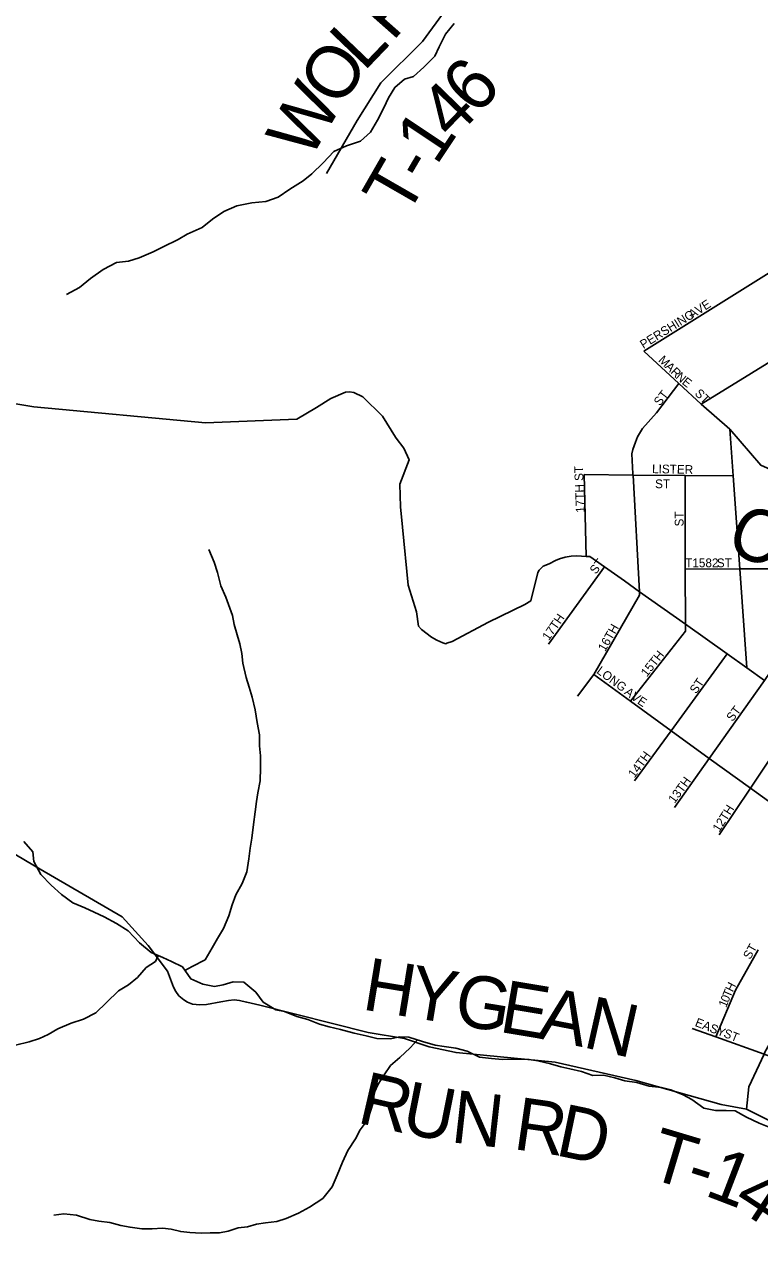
# Model space of a CAD drawing. Extents: x 1624196 to 2029251, y 146837 to 440034.
# Drawn here: x 1811228 to 1815416, y 273733 to 280739 of the extents above; entities that cross this region are included whole.
import ezdxf

# ---------------------------------------------------------------- set-up
doc = ezdxf.new("R2010")
doc.units = 0
for name, color, linetype in [('GM_X_County_Road', 7, 'Continuous'), ('GM_X_County_Road_Text', 7, 'Continuous'), ('GM_X_Minor_River', 7, 'Continuous'), ('GM_X_Township_Road', 7, 'Continuous'), ('GM_X_Township_Road_Text', 7, 'Continuous'), ('GM_X_Township_Subdivision', 7, 'Continuous'), ('GM_X_Township_Subdivision_Text', 7, 'Continuous')]:
    doc.layers.add(name, color=color, linetype=linetype)

msp = doc.modelspace()

# ---------------------------------------------------------------- linework, layer by layer
at = {"layer": 'GM_X_County_Road'}
for points in [[(1815247.1, 278432.8), (1815084.2, 278575.3), (1815920.9, 279089.6), (1816366.6, 279359.3), (1816614.9, 279007.9), (1816807.1, 279297), (1816979.5, 279252.7), (1817413.2, 279141), (1818042.4, 278972.6), (1818312.3, 278897.2), (1818447.3, 278884.8), (1818910.9, 278729.9), (1818861.8, 278488.5), (1819118.2, 278302.8), (1819417.6, 278085.8), (1819681.5, 277894.5), (1819933.5, 277729.6)], [(1811027, 278601), (1811280.7, 278559.4), (1812258.9, 278468.9), (1812779.5, 278490.3), (1812891.5, 278555.7), (1812973.4, 278606.8), (1813057.5, 278643.8), (1813079.9, 278645.4), (1813104.3, 278641), (1813156.3, 278616.7), (1813268, 278507.3), (1813341.6, 278387.6), (1813345.6, 278381.6), (1813390.4, 278323.8), (1813419.2, 278257.8), (1813366.3, 278118.6), (1813371.5, 277990.2), (1813382.8, 277873.8), (1813414.1, 277542.7), (1813461.9, 277390.5), (1813472.7, 277310.3), (1813490, 277290.7), (1813547.7, 277246.8), (1813577.5, 277229.1), (1813612, 277213.6), (1813623.1, 277210.5), (1813628.5, 277209.4), (1813635.4, 277211.7), (1813665.7, 277221.8), (1813872.6, 277332.4), (1814079.4, 277433), (1814112.8, 277453.3), (1814153.4, 277616.4), (1814160.1, 277628.8), (1814183.9, 277651), (1814217.9, 277665.5), (1814253.4, 277683.3), (1814277.3, 277694), (1814309, 277703.3), (1814343.5, 277708.8), (1814375.7, 277709.9), (1814376.1, 277709.9)], [(1815444.7, 277000.2), (1815345.2, 277072.1), (1815304.5, 277635.6), (1815266.3, 278165.9), (1815247.1, 278432.8)], [(1815247.1, 278432.8), (1815423.7, 278227.2), (1816086.3, 277932.4), (1816701, 277654.8), (1816789.8, 277607), (1816744.5, 277510.1), (1816661.4, 277372.7), (1816616.5, 277231.7), (1816607.8, 277145.5), (1816808.4, 276944.6), (1816903.8, 276849.1), (1817003, 276749.7), (1817272.5, 276611), (1817397.8, 276546.5), (1817554.1, 276467.1), (1817826.8, 276328.4), (1818051, 276214.5), (1818395, 276059.2), (1818745, 275886.4), (1818800.4, 275855.4), (1819072.9, 275695.9), (1819214.6, 275616.1)], [(1814376.1, 277709.9), (1814428.4, 277707), (1814450.1, 277705.8), (1814533.4, 277647.1), (1814646.6, 277567.2), (1814732.7, 277506.2), (1814994.3, 277320.8), (1815233.3, 277151.4), (1815345.2, 277072.1)]]:
    msp.add_lwpolyline(points, dxfattribs=at)
at = {"layer": 'GM_X_Minor_River'}
for points in [[(1813676.2, 280746.2), (1813627.6, 280684.2), (1813591, 280612.2), (1813566.6, 280560.2), (1813504, 280496.3), (1813445.4, 280442.5), (1813393.1, 280428.8), (1813338.6, 280380.9), (1813302.1, 280321), (1813275.6, 280264.9), (1813239.1, 280194.9), (1813200.5, 280126.9), (1813141.9, 280075.1), (1813063.5, 280047.5), (1812991, 280015.8), (1812930.4, 279951.9), (1812865.7, 279888.1), (1812815.3, 279848.2), (1812740.7, 279800.5), (1812674.2, 279754.8), (1812603.8, 279731.1), (1812523.4, 279723.6), (1812437, 279706), (1812364.5, 279674.3), (1812300, 279630.6), (1812239.5, 279582.8), (1812155, 279545.2), (1812102.6, 279513.4), (1812018, 279471.7), (1811961.6, 279444), (1811881.1, 279410.3), (1811820.8, 279390.6), (1811752.5, 279383), (1811676, 279343.3), (1811603.4, 279291.6), (1811540.8, 279239.8), (1811466.3, 279200.1)], [(1812141.7, 275347.1), (1812183.9, 275368.9), (1812256.4, 275406.6), (1812297, 275474.6), (1812327.4, 275528.6), (1812361.9, 275586.6), (1812392.5, 275658.6), (1812411, 275720.8), (1812431.4, 275776.8), (1812468, 275842.8), (1812494.5, 275908.9), (1812507, 275983.1), (1812513.4, 276043.2), (1812523.9, 276101.4), (1812532.4, 276179.6), (1812542.9, 276251.8), (1812549.3, 276309.9), (1812557.7, 276360), (1812570.2, 276428.2), (1812572.6, 276502.4), (1812573.1, 276570.7), (1812567.4, 276626.9), (1812567.8, 276689.1), (1812554.3, 276759.4), (1812542.7, 276831.7), (1812525.1, 276904.1), (1812507.4, 276962.4), (1812491.7, 277016.6), (1812472.2, 277099), (1812466.5, 277153.2), (1812454.8, 277209.5), (1812439.1, 277259.8), (1812423.4, 277318.1), (1812413.7, 277370.3), (1812374.3, 277474.9), (1812346.6, 277539.3), (1812327, 277615.6), (1812309.3, 277673.9), (1812277.7, 277746.4)], [(1815481.7, 274450.2), (1815415.6, 274476.7), (1815343.5, 274509.2), (1815277.5, 274545.7), (1815227.4, 274548), (1815165.2, 274548.4), (1815099, 274560.8), (1815031.1, 274611.4), (1814981.1, 274637.8), (1814911, 274666.3), (1814858.9, 274678.7), (1814788.7, 274687.1), (1814718.6, 274707.6), (1814648.4, 274718.1), (1814592.3, 274734.5), (1814528.2, 274748.9), (1814466, 274747.2), (1814401.9, 274769.7), (1814335.8, 274786.1), (1814283.6, 274796.5), (1814225.5, 274814.9), (1814153.4, 274831.4), (1814103.3, 274839.7), (1814027, 274840.2), (1813952.7, 274838.6), (1813888.5, 274845), (1813820.3, 274851.4), (1813750.3, 274886), (1813686.2, 274904.4), (1813620, 274912.8), (1813567.9, 274921.2), (1813495.8, 274941.7), (1813417.7, 274966.2), (1813367.5, 274968.5), (1813311.2, 274956.8), (1813235, 274959.3), (1813174.8, 274973.7), (1813106.7, 274988.1), (1813028.6, 275010.7), (1812964.4, 275025.1), (1812908.3, 275039.5), (1812842.3, 275066), (1812780.2, 275084.4), (1812710.1, 275112.9), (1812660, 275121.3), (1812588, 275165.8), (1812546.2, 275222.3), (1812478.4, 275278.9), (1812416.1, 275281.2), (1812359.8, 275265.5), (1812309.6, 275255.8), (1812243.4, 275268.2), (1812175.4, 275298.7), (1812127.7, 275367.2), (1812065.7, 275397.7), (1812015.6, 275420.1), (1811949.6, 275448.6), (1811883.7, 275503.1), (1811817.9, 275571.8), (1811751.9, 275614.3), (1811682, 275652.9), (1811623.9, 275679.3), (1811571.9, 275703.7), (1811503.8, 275732.2), (1811437.9, 275778.7), (1811380.1, 275833.3), (1811320.2, 275893.8), (1811280.6, 275968.3), (1811274.9, 276022.5), (1811223.1, 276081)], [(1811990.2, 275431.1), (1811973.3, 275398.3), (1811920.9, 275362.5), (1811872.4, 275306.6), (1811819.9, 275264.7), (1811763.5, 275231), (1811694.8, 275163.1), (1811634.2, 275105.3), (1811563.7, 275069.6), (1811493.3, 275045.9), (1811416.9, 275014.3), (1811362.4, 274980.5), (1811312.1, 274958.7), (1811253.8, 274939), (1811175.4, 274921.4)], [(1813468.3, 274950.3), (1813425.3, 274906), (1813366.7, 274850.1), (1813314.2, 274804.3), (1813277.8, 274752.3), (1813243.3, 274698.4), (1813220.9, 274648.3), (1813216.5, 274598.2), (1813200.1, 274544.1), (1813179.7, 274492), (1813141.2, 274438.1), (1813114.8, 274386.1), (1813070.2, 274320.1), (1813039.7, 274254.1), (1813009.1, 274180), (1812980.5, 274112), (1812927.9, 274046), (1812851.3, 273996.3), (1812788.9, 273962.6), (1812718.5, 273932.9), (1812666.1, 273915.2), (1812601.9, 273907.5), (1812549.6, 273899.8), (1812499.4, 273884), (1812445.1, 273878.3), (1812388.8, 273860.6), (1812338.6, 273850.9), (1812286.4, 273851.2), (1812234.2, 273849.5), (1812170, 273851.9), (1812117.8, 273858.2), (1812063.7, 273870.6), (1812013.6, 273876.9), (1811955.4, 273873.2), (1811897.1, 273873.6), (1811829, 273882), (1811776.8, 273892.4), (1811714.7, 273908.8), (1811650.6, 273917.2), (1811600.4, 273927.5), (1811524.3, 273952.1), (1811452.1, 273958.5), (1811393.9, 273950.8)]]:
    msp.add_lwpolyline(points, dxfattribs=at)
at = {"layer": 'GM_X_Township_Road'}
for points in [[(1812948.9, 279890), (1813122.9, 280193.1), (1813257.6, 280407.3), (1813496.6, 280642.7), (1813744.6, 280984.7), (1813868.8, 281239.1), (1813940.4, 281531), (1813981.8, 281820.7), (1814011.3, 281909.5), (1814070.7, 281984.3), (1814277.3, 282245.5), (1814452.4, 282444.1), (1814585.6, 282600.2), (1814782.5, 282821.1), (1814847.3, 282919), (1814875.4, 282986.7), (1814920.9, 283266.4), (1814929.3, 283445.2), (1814959.9, 283608.3)], [(1812494.3, 275165.3), (1812493.8, 275165.4), (1812453.8, 275174.8), (1812423.5, 275179.7), (1812390.1, 275175.2), (1812347.3, 275167.7), (1812265, 275152.8), (1812227.7, 275150.8), (1812185.5, 275155.2), (1812156.5, 275166.3), (1812136.5, 275179.7), (1812107.6, 275201.9), (1812089.8, 275226.4), (1812077, 275251.3), (1812041.9, 275343.4), (1811931.9, 275488.9), (1811783.6, 275652.1), (1811316.4, 275924.5), (1811140.4, 276029.2), (1810954.3, 276151.8), (1810793.5, 276351)], [(1816071.5, 273721.2), (1816095.5, 273940.3), (1816134.3, 274085.3), (1816137.5, 274165.7), (1816108.9, 274219.7), (1816077, 274258.8), (1816011.4, 274319.1), (1815832.1, 274351.5), (1815727.5, 274358.4), (1815650.9, 274373.7), (1815604.7, 274478), (1815478.9, 274486.5), (1815342.8, 274555.2), (1815198.4, 274582), (1814712.4, 274719.7), (1814253, 274823.5), (1813687.4, 274878), (1813534.2, 274910.6), (1813393, 274959.4), (1813185.5, 274993.4), (1812568.7, 275147.9), (1812494.3, 275165.3)]]:
    msp.add_lwpolyline(points, dxfattribs=at)
at = {"layer": 'GM_X_Township_Subdivision'}
for points in [[(1814756.7, 278878.1), (1815684.2, 279456.8), (1816409.7, 279896.6), (1816625.1, 280026.4), (1816695.5, 280050.2)], [(1815084.2, 278575.3), (1814957.8, 278692.2), (1814756.7, 278878.1)], [(1814695.7, 278177.1), (1814689.8, 278292.8), (1814694.3, 278317.7), (1814709.2, 278359.3), (1814721, 278388.8), (1814750.7, 278436), (1814830.3, 278525.2), (1814957.8, 278692.2)], [(1814379.5, 276909.7), (1814472.3, 277034.1), (1814733.8, 277485.8), (1814732.7, 277506.2), (1814696, 278171), (1814695.7, 278177.1)], [(1814417.5, 278173.5), (1814696, 278171), (1814992.8, 278168.4), (1815266.3, 278165.9)], [(1814428.4, 277707), (1814417.5, 278173.5)], [(1814681.5, 276882.1), (1814994.4, 277280.2), (1814994.3, 277320.8), (1814993.8, 277635), (1814992.8, 278168.4)], [(1814213.7, 277207.3), (1814533.4, 277647.1)], [(1814993.8, 277635), (1815304.5, 277635.6), (1815484.5, 277636)], [(1814933.3, 276275.7), (1815130.9, 276555.6), (1815444.7, 277000.2), (1815481.4, 277052.1), (1815646.9, 277270)], [(1814705, 276427), (1814913.8, 276713.3), (1815233.3, 277151.4)], [(1814472.3, 277034.1), (1814681.5, 276882.1), (1814913.8, 276713.3), (1815130.9, 276555.6), (1815364.7, 276385.7), (1815605.5, 276212.7), (1815833.6, 276048.9), (1816071.1, 275878.3), (1816299, 275714.6), (1816551.4, 275545.4), (1816792.9, 275383.7)], [(1815187.4, 276119.9), (1815364.7, 276385.7), (1815667.3, 276839.3), (1815755.6, 276971.7)], [(1815168.3, 274967.6), (1815280.6, 275233.6), (1815409, 275463.9)], [(1815342.8, 274555.2), (1815356.9, 274682.3), (1815442.6, 274868.8), (1815448.1, 274880.7), (1815733.3, 275389.7)], [(1815033.3, 275016.2), (1815168.3, 274967.6), (1815442.6, 274868.8), (1815766.2, 274752.3)]]:
    msp.add_lwpolyline(points, dxfattribs=at)

# ---------------------------------------------------------------- texts
at = {"layer": 'GM_X_County_Road_Text'}
msp.add_text('C-440', height=300, rotation=336.01021, dxfattribs=at).set_placement((1815212, 277749.6))
at = {"layer": 'GM_X_Township_Road_Text'}
for s, rotation, p in [('F', 48.522, (1813325.2, 280639)), ('L', 46.24556, (1813161.2, 280467.3)), ('O', 56.8848, (1813026.2, 280257.7)), ('6', 47.94539, (1813804.9, 280214.3)), ('W', 59.81415, (1812853.5, 279960.7)), ('4', 45.85004, (1813668, 280073)), ('1', 56.32436, (1813574.7, 279930.5)), ('T', 60.11744, (1813403.3, 279634.1)), ('-', 59.6132, (1813514.8, 279828.1)), ('H', 350.72153, (1813145.5, 275125.3)), ('Y', 350.72267, (1813406.1, 275082.7)), ('G', 350.72267, (1813666.6, 275040.2)), ('E', 350.47638, (1813926.8, 274997.6)), ('A', 348.89653, (1814146, 274960.9)), ('N', 347.28115, (1814402.9, 274910.5)), ('R', 346.989, (1813116.4, 274480.6)), ('U', 348.8275, (1813366.6, 274422.9)), ('N', 353.57091, (1813651.9, 274367.7)), ('R', 351.75757, (1814007.8, 274329.2)), ('D', 348.19605, (1814246.8, 274294.8)), ('T', 343.33319, (1814770.1, 274166.9)), ('1', 338.96156, (1815096.7, 274066.9)), ('-', 342.23526, (1814983.6, 274103)), ('4', 326.66067, (1815254, 274008.3))]:
    msp.add_text(s, height=300, rotation=rotation, dxfattribs=at).set_placement(p)
at = {"layer": 'GM_X_Township_Subdivision_Text'}
for s, rotation, p in [('AVE', 32.62284, (1815032.2, 279060.7)), ('PERSHING', 31.82754, (1814755.1, 278889.2)), ('M', 316.05615, (1814837, 278822)), ('A', 316.04332, (1814875, 278785.3)), ('R', 316.04619, (1814906.7, 278754.8)), ('N', 317.35874, (1814936.1, 278726.4)), ('E', 321.38924, (1814971.4, 278694.1)), ('ST', 52.43303, (1814849.4, 278561.4)), ('ST', 314.99504, (1815043.9, 278632.7)), ('17TH ST', 92.20139, (1814420.7, 277956.8)), ('LISTER', 358.77875, (1814804.3, 278182.2)), ('ST', 0.00001, (1814821.7, 278096.2)), ('ST', 90, (1814983.9, 277878)), ('ST', 53.13155, (1814484.2, 277602.1)), ('T1582', 0.00001, (1814993.3, 277645.4)), ('ST', 0.00001, (1815173.7, 277645.4)), ('17TH', 55.30353, (1814215.5, 277223.4)), ('16TH', 60.25679, (1814536.3, 277161.1)), ('15TH', 51.34125, (1814774.7, 277017.1)), ('LONG', 323.4302, (1814484.1, 277045.2)), ('ST', 55.30921, (1815055.9, 276919.8)), ('A', 321.73964, (1814642.8, 276926.1)), ('V', 324.83698, (1814679.7, 276897.1)), ('E', 326.27089, (1814716.8, 276871)), ('ST', 52.42653, (1815263, 276761.8)), ('14TH', 53.83939, (1814704.1, 276440.4)), ('13TH', 53.84687, (1814932.9, 276295.2)), ('12TH', 57.80544, (1815187.7, 276131.8)), ('ST', 60.25679, (1815363.5, 275405.5)), ('H', 63.2981, (1815264, 275219.9)), ('0', 67.07175, (1815238.6, 275160)), ('T', 67.04176, (1815250.6, 275188.3)), ('1', 67.03305, (1815226.6, 275131.6)), ('EASY', 338.50126, (1815045.1, 275031.2)), ('ST', 338.20236, (1815208, 274969.5))]:
    msp.add_text(s, height=50, rotation=rotation, dxfattribs=at).set_placement(p)

doc.saveas('drawing.dxf')
